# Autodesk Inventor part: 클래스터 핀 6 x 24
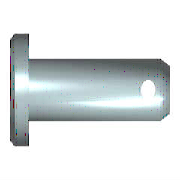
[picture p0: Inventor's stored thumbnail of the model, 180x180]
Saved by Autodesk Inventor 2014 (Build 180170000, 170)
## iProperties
IsCustomPart: 1
Created: 2012-02
Part Number: 클래스터 핀 6 x 24
Material: 강철
Description: 머리가 있는 클레비스 핀
Document SubType Name: Modeling
Standard: ISO 2341
Designer: mduedu
Standard Revision: Second edition 1986-11-01
Standards Organization: ISO
Language: ko-KR
Size Designation: B - 6 x 24
Categories: <MemberInstance><Categories><Category DisplayName="조임쇠" InternalName="e4da775c-781d-43d5-af7c-5136215cf5a6" Mnemonic="FSTN"><Category DisplayName="핀" InternalNa
Density: 7.85 g/cm^3
Appearance: 주황색
Author: mduedu
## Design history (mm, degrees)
sketch "스케치1"
  geometry: L1 (-2, 0)-(-2, 5); L2 (-2, 5)-(0, 5); L3 (0, 5)-(0, 3); L4 (0, 3)-(24, 3); L5 (24, 3)-(24, 0); L6 (-2, 0)-(24, 0); L7 (-4, 0)-(17, 0) reference; L8 (0, -0.98)-(0, 3.08) reference; C1 r 0.8 at (20.8, 0)
  constraints: 12 end point, 3 parallel, 2 collinear, 2 perpendicular, 1 centre point, 1 point on line, 1 vertical
  dimensions: "d0" = 6 diameter of L4 L6 (= NND); "d1" = 10 diameter of L2 L6 (= KOD); "d2" = 2 distance of L1.end L2.end (= KOH); "d3" = 24 distance of L3.end L4.end (= NLG); "d5" = 3.2 distance from line of L5 C1.centre (= DIST); "d6" = 1.6 diameter of C1 (= BOR)
revolve "본체" stored, may be unused: angle "d4" = 90 deg
extrude "구멍" cut sketch "스케치1" stored distance "d7" = 6 (= NND); taper "d8" = 0 deg
workaxis "Work Axis1"
workplane "Work Plane1"
body "Solid1"
chamfer "모따기1" distance "d9" = 1 (= PHH2); stored, may be unused: angle "d10" = 45 deg (= FAWI2), second distance "d16" = 1 (= PHH2)
chamfer "모따기2" distance "d11" = 2 (= PHH1); stored, may be unused: angle "d12" = 30 deg (= FAWI1), second distance "d17" = 2 (= PHH1)
other parameters: "PHH1" = 2 [user parameter; used in 2 equation terms], "PHH2" = 1 [user parameter; used in 2 equation terms], "KOD" = 10 [user parameter; used in 1 equation term], "KOH" = 2 [user parameter; used in 1 equation term], "NND" = 6 [user parameter; used in 2 equation terms], "FAWI1" = 30 deg [user parameter; used in 1 equation term], "FAWI2" = 45 deg [user parameter; used in 1 equation term], "DIST" = 3.2 [user parameter; used in 1 equation term], "BOR" = 1.6 [user parameter; used in 1 equation term], "NLG" = 24 [user parameter; used in 1 equation term], "d13" = 0, "d14" = 0, "d27" = 0, "d28" = 0, "d29" = 0, "d30" = 0, "d31" = 0
